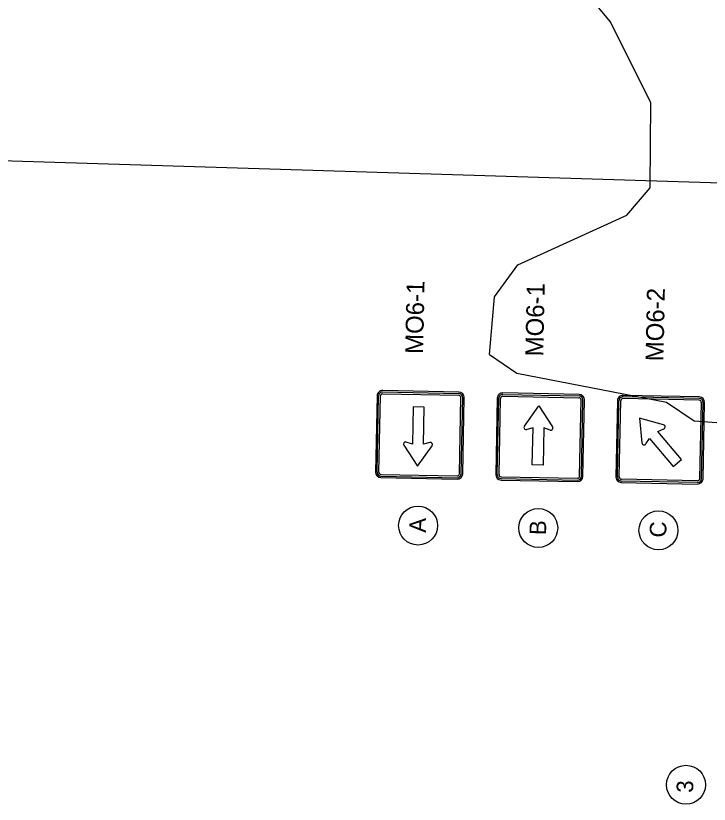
# Model space of a CAD drawing. Extents: x 331323 to 388339, y 121519 to 205315.
# Drawn here: x 363194 to 365701, y 140511 to 143362 of the extents above; entities that cross this region are included whole.
import ezdxf

# ---------------------------------------------------------------- set-up
doc = ezdxf.new("R2010")
doc.units = 0
for name, color, linetype in [('CA-TEXT', 7, 'Continuous'), ('Level 4', 7, 'Continuous'), ('Level 57', 7, 'Continuous'), ('P_SGN_Cell', 7, 'Continuous')]:
    doc.layers.add(name, color=color, linetype=linetype)

msp = doc.modelspace()

# ---------------------------------------------------------------- linework, layer by layer
at = {"layer": 'CA-TEXT'}
for centre in [(364648.6, 141519.1), (365083.2, 141510.3), (365517.8, 141501.6), (365617.4, 140581.8)]:
    msp.add_circle(centre, 70.4, dxfattribs=at)
at = {"layer": 'Level 4'}
msp.add_lwpolyline([(367338.6, 142707.9), (362672.8, 142853), (355637.9, 142792.5)], dxfattribs=at)
at = {"layer": 'Level 57'}
for points in [[(364906.3, 142137.4), (364924.9, 142345.6), (365009.4, 142461.5), (365403, 142641.2), (365487.4, 142740.5), (365490.2, 143048.8), (365342.8, 143341.8), (365260.3, 143442.5)], [(364906.3, 142137.4), (365005.8, 142069.8), (365546.9, 141964.9), (365646.4, 141897.3), (366171.4, 141859.3), (366245.9, 141791.9), (366491.8, 141331.3), (366656.8, 141138.2), (366848, 141069.8), (367014.6, 141051.6)]]:
    msp.add_lwpolyline(points, dxfattribs=at)
at = {"layer": 'P_SGN_Cell'}
for p, q in [((364500.5, 141988), (364494.9, 141712.5)), ((364500.2, 141712.4), (364505.7, 141987.9)), ((364506.7, 141712.2), (364512.3, 141987.8)), ((364520.3, 141995.5), (364795.9, 141990)), ((364520.5, 142002.1), (364796, 141996.5)), ((364796.1, 142001.8), (364520.6, 142007.3)), ((364955, 141986.8), (365230.5, 141981.2)), ((364955.1, 141993.3), (365230.6, 141987.8)), ((365230.8, 141993), (364955.2, 141998.6)), ((365665.3, 141979), (365389.7, 141984.6)), ((365665.4, 141984.3), (365389.8, 141989.8)), ((364798.1, 141706.4), (364803.6, 141981.9)), ((364804.6, 141706.2), (364810.2, 141981.8)), ((364809.9, 141706.1), (364815.4, 141981.7)), ((364935.1, 141979.3), (364929.6, 141703.7)), ((364934.8, 141703.6), (364940.4, 141979.2)), ((364941.4, 141703.5), (364946.9, 141979)), ((365232.7, 141697.6), (365238.2, 141973.2)), ((365239.2, 141697.5), (365244.8, 141973.1)), ((365244.5, 141697.4), (365250, 141972.9)), ((365369.7, 141970.5), (365364.2, 141695)), ((365369.4, 141694.9), (365375, 141970.4)), ((365376, 141694.7), (365381.5, 141970.3)), ((365665.1, 141972.5), (365389.6, 141978)), ((365667.3, 141688.9), (365672.9, 141964.4)), ((365673.9, 141688.7), (365679.4, 141964.3)), ((365679.1, 141688.6), (365684.7, 141964.2)), ((364631.1, 141948.3), (364628.4, 141813.8)), ((364670.5, 141947.5), (364631.1, 141948.3)), ((364667.8, 141813), (364670.5, 141947.5)), ((365033.1, 141878.5), (365085.7, 141951.8)), ((365085.7, 141951.8), (365135.3, 141876.5)), ((365536.2, 141883.8), (365449.9, 141908)), ((365449.9, 141908), (365458.2, 141818.2)), ((365064.4, 141872.7), (365041.6, 141866.3)), ((365061.7, 141738.3), (365064.4, 141872.7)), ((365103.8, 141871.9), (365101, 141737.5)), ((365126.3, 141864.6), (365103.8, 141871.9)), ((365515.9, 141859.5), (365537.6, 141868.8)), ((365600.9, 141757.6), (365515.9, 141859.5)), ((364628.4, 141813.8), (364605.9, 141821.1)), ((364690.6, 141819.4), (364667.8, 141813)), ((365472.6, 141814.6), (365485.6, 141834.3)), ((365485.6, 141834.3), (365570.6, 141732.4)), ((364596.9, 141809.3), (364646.5, 141734)), ((364646.5, 141734), (364699.1, 141807.2)), ((365570.6, 141732.4), (365600.9, 141757.6)), ((365101, 141737.5), (365061.7, 141738.3)), ((364514.5, 141704.2), (364790, 141698.7)), ((364514.2, 141692.4), (364789.8, 141686.8)), ((364514.3, 141697.6), (364789.9, 141692.1)), ((364948.8, 141683.6), (365224.4, 141678.1)), ((364949, 141688.9), (365224.5, 141683.3)), ((364949.1, 141695.4), (365224.7, 141689.9)), ((365383.5, 141674.9), (365659, 141669.3)), ((365659.1, 141674.6), (365383.6, 141680.1)), ((365659.3, 141681.1), (365383.7, 141686.7))]:
    msp.add_line(p, q, dxfattribs=at)
for centre, radius, start, end in [((364520.2, 141987.6), 19.7, 88.8468, 178.8468), ((364520.2, 141987.6), 19.7, 149.4503, 178.8468), ((364520.2, 141987.6), 14.4, 88.8468, 178.8468), ((364520.2, 141987.6), 7.87, 88.8468, 178.8468), ((364795.7, 141982.1), 7.87, 358.8468, 88.8468), ((364795.7, 141982.1), 14.4, 358.8468, 88.8468), ((364795.7, 141982.1), 19.7, 358.8468, 88.8468), ((364954.8, 141978.9), 19.7, 88.8468, 178.8468), ((364954.8, 141978.9), 19.7, 149.4503, 178.8468), ((364954.8, 141978.9), 14.4, 88.8468, 178.8468), ((364954.8, 141978.9), 7.87, 88.8468, 178.8468), ((365230.4, 141973.3), 14.4, 358.8468, 88.8468), ((365230.4, 141973.3), 19.7, 358.8468, 88.8468), ((365389.4, 141970.1), 19.7, 88.8462, 178.8462), ((365389.4, 141970.1), 14.4, 88.8462, 178.8462), ((365665, 141964.6), 19.7, 358.8462, 88.8462), ((365230.4, 141973.3), 7.87, 358.8468, 88.8468), ((365389.4, 141970.1), 7.88, 88.8462, 178.8462), ((365665, 141964.6), 7.88, 358.8462, 88.8462), ((365665, 141964.6), 14.4, 358.8462, 88.8462), ((365039.5, 141873.9), 7.87, 144.316, 285.6482), ((365128.7, 141872.1), 7.87, 252.043, 33.3753), ((365534.6, 141876.1), 7.87, 292.7827, 77.9371), ((364603.5, 141813.6), 7.87, 72.0442, 213.3765), ((364692.7, 141811.8), 7.87, 324.3172, 105.6494), ((365466, 141818.9), 7.88, 185.2961, 326.6328), ((364514.6, 141712.1), 19.7, 178.8468, 268.8468), ((364514.6, 141712.1), 14.4, 178.8468, 268.8468), ((364514.6, 141712.1), 7.87, 178.8468, 268.8468), ((364790.2, 141706.5), 19.7, 268.8468, 358.8468), ((364790.2, 141706.5), 14.4, 268.8468, 358.8468), ((364790.2, 141706.5), 7.87, 268.8468, 358.8468), ((364949.2, 141703.3), 19.7, 178.8468, 268.8468), ((364949.2, 141703.3), 14.4, 178.8468, 268.8468), ((364949.2, 141703.3), 7.87, 178.8468, 268.8468), ((365224.8, 141697.8), 19.7, 268.8468, 358.8468), ((365224.8, 141697.8), 14.4, 268.8468, 358.8468), ((365224.8, 141697.8), 7.87, 268.8468, 358.8468), ((365383.9, 141694.6), 19.7, 178.8462, 213.1868), ((365383.9, 141694.6), 19.7, 178.8462, 268.8462), ((365383.9, 141694.6), 14.4, 178.8462, 268.8462), ((365383.9, 141694.6), 19.7, 244.1347, 268.8462), ((365383.9, 141694.6), 7.88, 178.8462, 268.8462), ((365659.4, 141689), 19.7, 268.8462, 358.8462), ((365659.4, 141689), 14.4, 268.8462, 358.8462), ((365659.4, 141689), 7.88, 268.8462, 358.8462)]:
    msp.add_arc(centre, radius, start, end, dxfattribs=at)

# ---------------------------------------------------------------- texts
at = {"layer": 'CA-TEXT'}
for s, p in [('A', (364676.8, 141493)), ('B', (365111.4, 141484.2)), ('C', (365546, 141475.5)), ('3', (365643.2, 140552.4))]:
    msp.add_text(s, height=60, rotation=88.8468, dxfattribs=at).set_placement(p)
at = {"layer": 'P_SGN_Cell'}
for s, rotation, p in [('MO6-1', 88.8468, (364666.7, 142139.1)), ('MO6-1', 88.8468, (365101.4, 142130.4)), ('MO6-2', 88.8462, (365535.8, 142112.6))]:
    msp.add_text(s, height=64.8, rotation=rotation, dxfattribs=at).set_placement(p)

doc.saveas('drawing.dxf')
